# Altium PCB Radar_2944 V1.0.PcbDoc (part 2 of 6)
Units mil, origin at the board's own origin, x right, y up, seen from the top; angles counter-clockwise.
Board outline 3544.83 x 2556.65 mil, 8 copper layers (Top Layer, GND1, SIG1, PWR1, PWR2, SIG2, GND2, Bottom Layer), stack 55.2 mil thick; 301 components, 253 nets, 1055 pads, 1340 vias.
Unrouted connection lines stored in the file: 12.
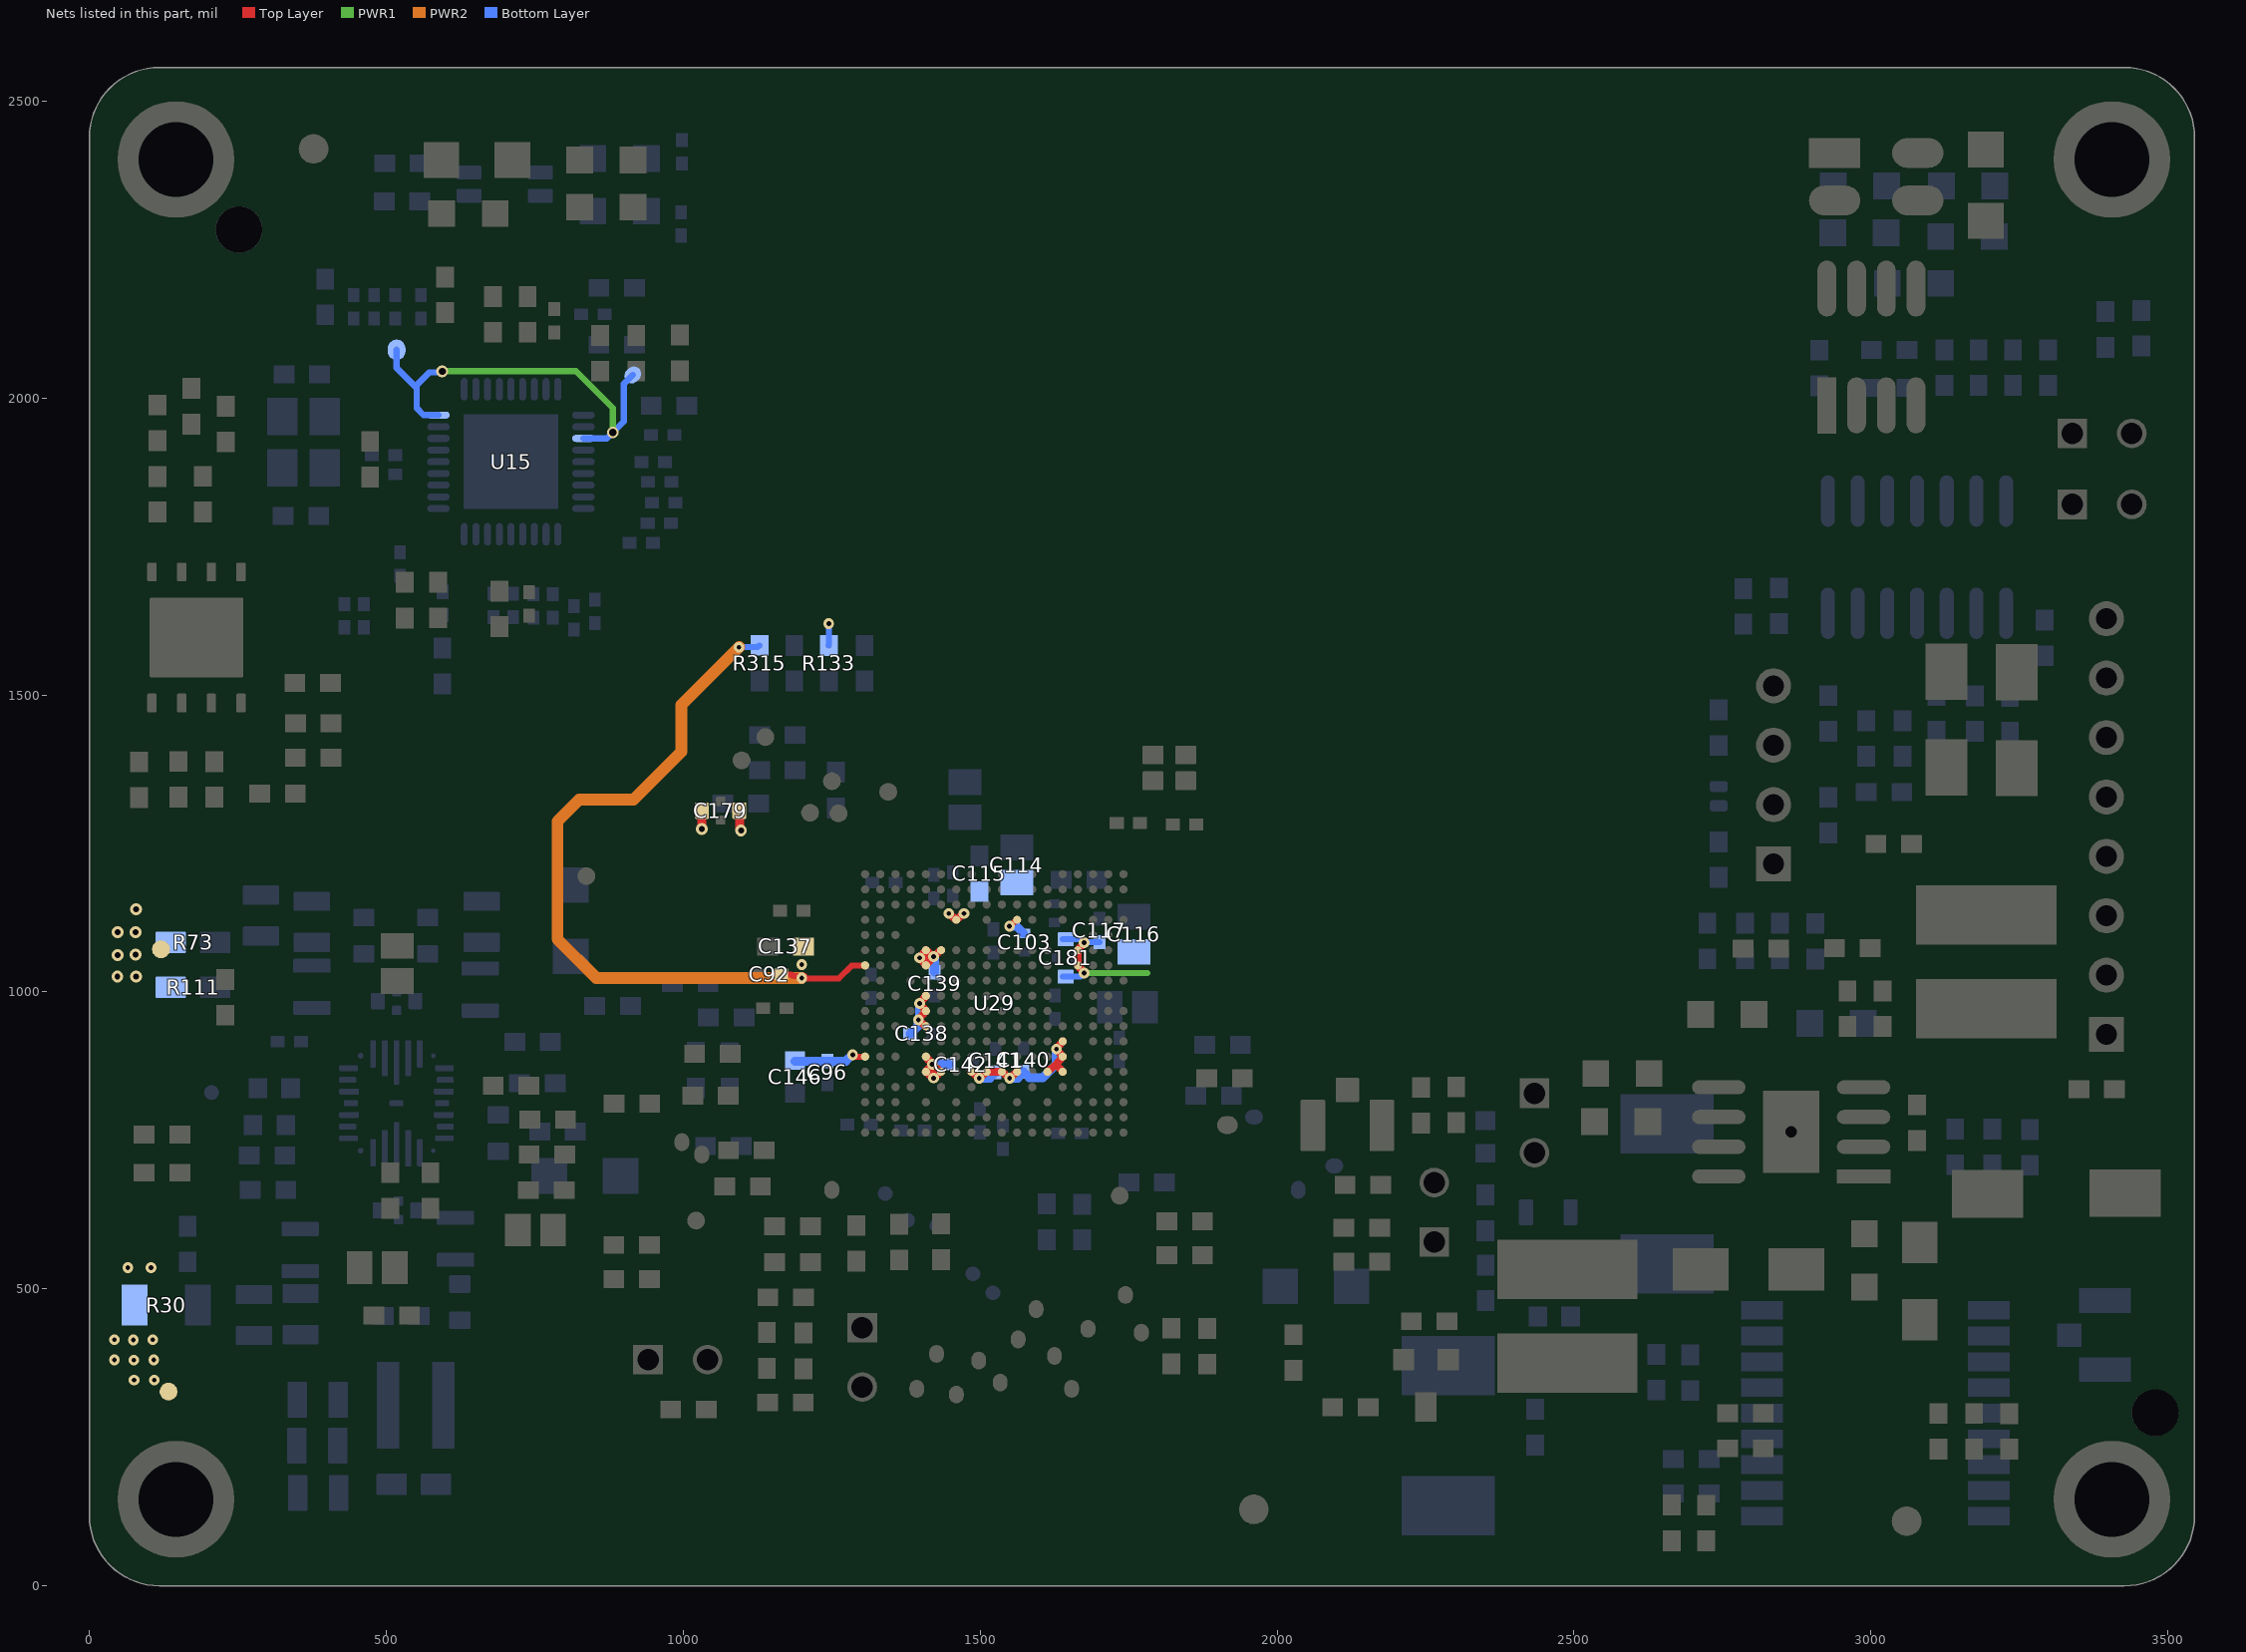
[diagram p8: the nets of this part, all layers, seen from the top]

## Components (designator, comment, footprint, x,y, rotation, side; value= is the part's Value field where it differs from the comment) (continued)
R267 "CRCW040210R0JNED" 0603 983.72,296.92 r0 top value=10
R270 "CRCW04020000Z0EDHP" 0603 502.24,2395.17 r0 bottom value=0
R271 "CRCW040210K0FKED" 0603 1883.07,910.88 r0 bottom value=10.0k
R272 "CRCW040210K0FKED" 0603 1886.6,854.78 r0 top value=10.0k
R273 "CRCW040210K0FKED" 0603 1070.9,824.97 r180 top value=10.0k
R275 "ERJ-P06F1001V" 0805 825.64,2400.56 r0 top value=1.00k
R276 "CRCW04022K94FKED" 0603 1036.73,1015.17 r180 bottom value=2.94k
R277 "CRCW04022K94FKED" 0603 1021.31,843.39 r90 bottom value=2.94k
R278 "CRCW0402100KFKED" 0603 1612.22,637.98 r270 bottom value=100k
R279 "CRCW0402100KFKED" 0603 1671.61,637.58 r270 bottom value=100k
R280 "CRCW04022K20JNED" 0603 594.45,1573.76 r270 bottom value=2.2k
R281 "ERJ-P06F1001V" 0805 825.64,2321.31 r0 top value=1.00k
R282 "CRCW0805100KJNEA" 0805 593.31,2310.39 r0 top value=100k
R291 "ERJ-2GE0R00X" 0603 165.54,600.43 r270 bottom value=0
R292 "CRCW04022K20JNED" 0603 779.35,846.19 r180 bottom value=2.2k
R309 "CRCW040210K0FKED" 0603 1819.45,556.76 r0 top value=10.0k
R312 "CRCW040210K0FKED" 0603 1869.45,613.76 r180 top value=10.0k
R315 "CRCW04021K00FKED" 0603 1128.42,1528.52 r90 bottom value=1.00k
R316 "ERJ-2GE0R00X" 0603 1133.51,1373.6 r0 bottom value=0
R326 "CRCW040210K0FKED" 0603 1074.9,672.54 r0 top value=10.0k
R331 "CRCW04021K00FKED" 0603 1882.33,378.28 r90 top value=1.00k
R332 "CRCW04021K00FKED" 0603 2943.45,1073.76 r0 top value=1.00k
R333 "ERJ-2GEJ101X" 0603 2169.45,674.76 r180 top value=100
R334 "CRCW02010000Z0ED" 0603 2167.45,602.76 r180 top value=0
R335 "CRCW040210K0FKED" 0603 2117.45,545.76 r0 top value=10.0k
R347 "ERJ-2GEJ511X" 0603 2242.09,784.19 r90 top value=510
R350 "NC.10K" 0402 516.58,2208 r0 bottom value=10.0k
R380 "CRCW040233R2FKED" 0603 1042.45,740.76 r0 bottom value=33.2
R381 "CRCW040233R2FKED" 0603 1024.22,895.77 r0 top value=33.2
R386 "CRCW040233R2FKED" 0603 1918.03,824.97 r180 bottom value=33.2
R392 "CRCW040233R2FKED" 0603 1081.13,733.32 r0 top value=33.2
R409 "CRCW040210K0FKED" 0603 2350.98,535.04 r270 bottom value=10.0k
RC31 "1K" 0603 2743.51,1469.88 r270 bottom
RC32 "1K" 0603 2928.04,1272.69 r90 bottom
RC33 "1K" 0603 2743.51,1247.68 r270 bottom
RCN1 "10K" 0805 3027.45,2192.77 r0 bottom
RCN2 "10K" 0805 3207.45,2271.76 r180 bottom
RCN3 "10K" 0805 3026.39,2356.76 r180 bottom
RCN4 "120R" 1206 3193.15,2358.02 r270 top
RCN5 "10K" 0805 3208.45,2356.76 r180 bottom
RCN11 "10K" 0603 1202.56,420.61 r270 top
RCN12 "10K" 0603 1159.01,605.45 r0 top
RCN13 "10K" 0603 2724.52,1060.75 r90 bottom
RCN14 "10K" 0603 1147.01,308.76 r0 top
RCN15 "10K" 0603 2846.47,1110.73 r270 bottom
RCN17 "100k" 0603 2788.1,1060.75 r90 bottom
RCN18 "100k" 0603 1159.01,544.86 r0 top
RCN19 "100k" 0603 1140.74,421.35 r270 top
RCN24 "NC.0" 0603 1197.56,485.87 r180 top
RCN25 "0" 0603 2906.19,1060.14 r90 bottom
RG1 "10K" 0603 2813.54,231.54 r180 top
RG2 "10" 0603 2813.54,290.49 r180 top
RG9 "10" 0603 2638.45,384.76 r270 bottom
RGP1 "100" 0603 2722.19,155.54 r180 bottom
RGP2 "100" 0603 2722.19,213.41 r180 bottom
Rs301 "CRCW040210K0FKED" 0603 2845,1625 r90 bottom value=10.0k
Rs303 "CRCW040210K0FKED" 0603 2785,1674 r270 bottom value=10.0k
TP8 "TESTPOINT" TP_25MIL-SMT 205.67,830.62 r270 bottom
TRS1 "B82793S0513N201" TRS1 3034.6,2233.79 r90 top
TVS2 "SMF30A" DIODE3715 3082,513 r90 top
U5 "TCAN1043ADYYRQ1" D014_N 3077.45,1732 r270 bottom
U6 "SCT2632QSTER" PSOP-PAD 2865.53,764.38 r180 top
U8 "LP877451A1RXVRQ1" RXV0028A 640.11,792.6 r180 bottom
U9 "GD25B64CWAG" WSON-8L 131.93,1763.86 r270 top
U15 "DP83TC812R-Q1" TJA1100 864.96,2059.6 r270 bottom
U27 "TPS78417QDBVRQ1" DBV0005A-MFG 2456.45,577.76 r90 bottom
U29 "XA2944BGALT" 0-MFG 1523.74,980.65 r270 top locked
UCAN1 "TJ1051T/3" TJ1051T/3 3139.7,2103.46 r180 top
Y3 "FW4000044Q" FP-FW4000044Q_4-SMD-2.0x1.6mm-MFG 1818.6,1377.23 r0 top
YE7 "25M" 3225 362.25,1830.6 r180 bottom

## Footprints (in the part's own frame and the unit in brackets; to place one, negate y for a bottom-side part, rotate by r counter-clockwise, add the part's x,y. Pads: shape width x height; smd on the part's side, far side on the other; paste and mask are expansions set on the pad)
0-MFG [mm]
  round 0.35 smd paste+0 mask+0.05: A1(-5.525,5.525) A2(-4.875,5.525) A4(-3.575,5.525) A6(-2.275,5.525) A8(-0.975,5.525) A10(0.325,5.525) A11(0.975,5.525) A12(1.625,5.525) A13(2.275,5.525) A14(2.925,5.525) A15(3.575,5.525) A16(4.225,5.525) A17(4.875,5.525) A18(5.525,5.525) B1(-5.525,4.875) B2(-4.875,4.875) B3(-4.225,4.875) B4(-3.575,4.875) B5(-2.925,4.875) B6(-2.275,4.875) B7(-1.625,4.875) B8(-0.975,4.875) B9(-0.325,4.875) B10(0.325,4.875) B11(0.975,4.875) B12(1.625,4.875) B13(2.275,4.875) B14(2.925,4.875) B15(3.575,4.875) B16(4.225,4.875) B17(4.875,4.875) B18(5.525,4.875) C1(-5.525,4.225) C2(-4.875,4.225) C3(-4.225,4.225) C4(-3.575,4.225) C5(-2.925,4.225) C6(-2.275,4.225) C7(-1.625,4.225) C8(-0.975,4.225) C9(-0.325,4.225) C10(0.325,4.225) C11(0.975,4.225) C12(1.625,4.225) C14(2.925,4.225) C16(4.225,4.225) C17(4.875,4.225) C18(5.525,4.225) D1(-5.525,3.575) D2(-4.875,3.575) D3(-4.225,3.575) D6(-2.275,3.575) D7(-1.625,3.575) D9(-0.325,3.575) D11(0.975,3.575) D13(2.275,3.575) D15(3.575,3.575) D16(4.225,3.575) D17(4.875,3.575) D18(5.525,3.575) E1(-5.525,2.925) E2(-4.875,2.925) E3(-4.225,2.925) E4(-3.575,2.925) E11(0.975,2.925) E12(1.625,2.925) E13(2.275,2.925) E14(2.925,2.925) E15(3.575,2.925) E17(4.875,2.925) E18(5.525,2.925) F2(-4.875,2.275) F3(-4.225,2.275) F6(-2.275,2.275) F7(-1.625,2.275) F8(-0.975,2.275) F9(-0.325,2.275) F10(0.325,2.275) F11(0.975,2.275) F12(1.625,2.275) F13(2.275,2.275) F14(2.925,2.275) F16(4.225,2.275) F17(4.875,2.275) F18(5.525,2.275) G1(-5.525,1.625) G2(-4.875,1.625) G3(-4.225,1.625) G4(-3.575,1.625) G6(-2.275,1.625) G7(-1.625,1.625) G8(-0.975,1.625) G9(-0.325,1.625) G10(0.325,1.625) G11(0.975,1.625) G12(1.625,1.625) G13(2.275,1.625) G14(2.925,1.625) G15(3.575,1.625) G17(4.875,1.625) G18(5.525,1.625) H2(-4.875,0.975) H3(-4.225,0.975) H4(-3.575,0.975) H6(-2.275,0.975) H7(-1.625,0.975) H8(-0.975,0.975) H9(-0.325,0.975) H10(0.325,0.975) H11(0.975,0.975) H12(1.625,0.975) H13(2.275,0.975) H14(2.925,0.975) H16(4.225,0.975) H17(4.875,0.975) H18(5.525,0.975) J1(-5.525,0.325) J2(-4.875,0.325) J3(-4.225,0.325) J6(-2.275,0.325) J7(-1.625,0.325) J8(-0.975,0.325) J9(-0.325,0.325) J10(0.325,0.325) J11(0.975,0.325) J12(1.625,0.325) J13(2.275,0.325) J14(2.925,0.325) J15(3.575,0.325) J17(4.875,0.325) J18(5.525,0.325) K2(-4.875,-0.325) K3(-4.225,-0.325) K4(-3.575,-0.325) K6(-2.275,-0.325) K7(-1.625,-0.325) K8(-0.975,-0.325) K9(-0.325,-0.325) K10(0.325,-0.325) K11(0.975,-0.325) K12(1.625,-0.325) K13(2.275,-0.325) K14(2.925,-0.325) K16(4.225,-0.325) K17(4.875,-0.325) K18(5.525,-0.325) L1(-5.525,-0.975) L2(-4.875,-0.975) L3(-4.225,-0.975) L6(-2.275,-0.975) L7(-1.625,-0.975) L8(-0.975,-0.975) L9(-0.325,-0.975) L10(0.325,-0.975) L11(0.975,-0.975) L12(1.625,-0.975) L13(2.275,-0.975) L14(2.925,-0.975) L15(3.575,-0.975) L17(4.875,-0.975) L18(5.525,-0.975) M2(-4.875,-1.625) M3(-4.225,-1.625) M4(-3.575,-1.625) M6(-2.275,-1.625) M7(-1.625,-1.625) M8(-0.975,-1.625) M9(-0.325,-1.625) M10(0.325,-1.625) M11(0.975,-1.625) M12(1.625,-1.625) M13(2.275,-1.625) M14(2.925,-1.625) M16(4.225,-1.625) M17(4.875,-1.625) M18(5.525,-1.625) N1(-5.525,-2.275) N2(-4.875,-2.275) N3(-4.225,-2.275) N6(-2.275,-2.275) N7(-1.625,-2.275) N8(-0.975,-2.275) N9(-0.325,-2.275) N10(0.325,-2.275) N11(0.975,-2.275) N12(1.625,-2.275) N13(2.275,-2.275) N14(2.925,-2.275) N15(3.575,-2.275) N17(4.875,-2.275) N18(5.525,-2.275) P1(-5.525,-2.925) P2(-4.875,-2.925) P3(-4.225,-2.925) P6(-2.275,-2.925) P7(-1.625,-2.925) P8(-0.975,-2.925) P9(-0.325,-2.925) P10(0.325,-2.925) P11(0.975,-2.925) P12(1.625,-2.925) P13(2.275,-2.925) P14(2.925,-2.925) P16(4.225,-2.925) P17(4.875,-2.925) P18(5.525,-2.925) R1(-5.525,-3.575) R2(-4.875,-3.575) R3(-4.225,-3.575) R4(-3.575,-3.575) R6(-2.275,-3.575) R8(-0.975,-3.575) R10(0.325,-3.575) R12(1.625,-3.575) R14(2.925,-3.575) R15(3.575,-3.575) R17(4.875,-3.575) R18(5.525,-3.575) T1(-5.525,-4.225) T2(-4.875,-4.225) T3(-4.225,-4.225) T5(-2.925,-4.225) T7(-1.625,-4.225) T9(-0.325,-4.225) T11(0.975,-4.225) T13(2.275,-4.225) T15(3.575,-4.225) T16(4.225,-4.225) T17(4.875,-4.225) T18(5.525,-4.225) U1(-5.525,-4.875) U2(-4.875,-4.875) U3(-4.225,-4.875) U4(-3.575,-4.875) U5(-2.925,-4.875) U6(-2.275,-4.875) U7(-1.625,-4.875) U8(-0.975,-4.875) U9(-0.325,-4.875) U10(0.325,-4.875) U11(0.975,-4.875) U12(1.625,-4.875) U13(2.275,-4.875) U14(2.925,-4.875) U15(3.575,-4.875) U16(4.225,-4.875) U17(4.875,-4.875) U18(5.525,-4.875) V1(-5.525,-5.525) V2(-4.875,-5.525) V3(-4.225,-5.525) V4(-3.575,-5.525) V5(-2.925,-5.525) V6(-2.275,-5.525) V7(-1.625,-5.525) V8(-0.975,-5.525) V9(-0.325,-5.525) V10(0.325,-5.525) V11(0.975,-5.525) V12(1.625,-5.525) V13(2.275,-5.525) V14(2.925,-5.525) V15(3.575,-5.525) V16(4.225,-5.525) V17(4.875,-5.525) V18(5.525,-5.525)
  silkscreen extent -6.97,-6.12 6.12,6.12, body extent -6.58,-6.58 6.58,6.58, height 0.25
100uF [mm]
  rect 2.54x4 smd: 1(-3.048,0) 2(2.952,0)
  silkscreen extent -5.84,-2.54 4.77,2.55
0402 [mm]
  rect 0.5x0.6 smd: 1(-0.038,1.888) 2(-0.038,0.888)
  silkscreen extent -0.39,0.49 0.31,2.29, body extent -0.34,0.84 0.26,1.94, height 0.6
0603 [mil]
  rect 35x30 smd: 1(-5,0) 2(55,0)
  silkscreen extent -30,-25 80,25
0603L [mm] "0603 from SM-752 data"
  rect 0.8x0.85 smd: 1(-0.7,0) 2(0.7,0)
  silkscreen extent -0.07,-0.33 0.07,0.33, body extent -0.87,-0.47 0.87,0.47, height 1
0805 [mil]
  rect 45x45 smd: 1(0,0) 2(90,0)
  silkscreen extent -35,-35 124,35
0805_155 [mm] "SMD, 2-Leads, Body 2x1.25mm"
  rrect12% 0.825x1.55 smd: 1(-0.875,0) 2(0.875,0)
  silkscreen extent -0.15,-0.77 0.15,0.77, body extent -1.15,-0.77 1.15,0.77, height 1.55
0805L [mm]
  rect 1.1x1.4 smd: 1(-0.905,1.608) 2(0.595,1.608)
  silkscreen extent -1.58,0.81 1.27,2.41, body extent -1.25,0.88 0.94,2.33, height 1.45
1206 [mil]
  rect 60x60 smd: 1(-60,0) 2(60,0)
  silkscreen extent -100,-40 100,40
1206L [mm] "1206 from SM-752 data"
  rect 1.1x1.75 smd: 1(-1.35,0) 2(1.35,0)
  silkscreen extent -0.4,-0.77 0.4,0.77, body extent -1.7,-0.9 1.7,0.9, height 1.35
2016 [mm]
  rrect17% 1.6x0.6 smd far side: 1(1.942,0.914) 2(1.942,-0.886)
  body extent 1.04,-1.09 2.84,1.11, height 1
3225 [mm]
  rect 1.3x1.6 smd: 1(-0.86,3.505) 2(0.94,1.305) 3(-0.86,1.305) 4(0.94,3.505)
  silkscreen extent -2.02,0.81 1.29,4.79
ACT1210L-201-2P-TL00 [mm]
  rrect17% 1.05x0.6 smd paste+0 mask+0: 1(-1.55,2.778) 2(-1.55,1.778) 3(1.5,1.778) 4(1.5,2.778)
  silkscreen extent -1.85,0.93 1.68,4.15, body extent -1.97,1.03 1.93,3.53, height 2.5
"CAP.2/.4 - duplicate" [mil]
  rect 80x120 smd: 1(-41,-295) 2(-42,-63)
  silkscreen extent -179,-319 97,-38
D014_N [mm] "SOIC, 14-Leads, Body 8.7x3.9mm, Pitch 1.27m"
  oval 2.2x0.6 smd: 1(-2.4,3.81) 2(-2.4,2.54) 3(-2.4,1.27) 4(-2.4,0) 5(-2.4,-1.27) 6(-2.4,-2.54) 7(-2.4,-3.81) 8(2.4,-3.81) 9(2.4,-2.54) 10(2.4,-1.27) 11(2.4,0) 12(2.4,1.27) 13(2.4,2.54) 14(2.4,3.81)
  silkscreen extent -4.31,-4.57 2.41,4.57
DBV0005A-MFG [mm]
  rrect17% 1.1x0.6 smd paste+0 mask+0: 1(-1.3,0.95) 2(-1.3,0) 3(-1.3,-0.95) 4(1.3,-0.95) 5(1.3,0.95)
  silkscreen extent -1.5,-1.53 0.87,2.01, body extent -1.4,-1.45 1.4,1.45, height 1.45
DIOD-ES1D [mm] "D?"
  rect 1.8x2.4 smd: A(0,4.1) K(0,0)
  silkscreen extent -1.3,-1.9 1.3,5.7
DIODE3715 [mil]
  rect 70x60 smd: A(-65,0) K(65,0)
  silkscreen extent -110,-40 110,40
FP-FW4000044Q_4-SMD-2.0x1.6mm-MFG [mm]
  rrect13% 0.9x0.8 smd paste+0 mask+0: 1(-0.7,-0.55) 2(0.7,-0.55) 3(0.7,0.55) 4(-0.7,0.55)
  silkscreen extent -1,-1.89 1,1.35, body extent -1.25,-1.05 1.25,1.05, height 0.25
FP-GCJ188C70J475KE02J_0603-MFG [mm]
  rrect13% 0.75x0.9 smd paste+0 mask+0: 1(-0.775,0) 2(0.775,0)
  silkscreen extent -0.9,-0.87 0.9,0.87, body extent -0.8,-0.4 0.8,0.4, height 1
FP-GRT155R70J105KE01D_0402-MFG [mm]
  rrect25% 0.4x0.5 smd paste+0 mask+0: 1(-0.4,0) 2(0.4,0)
  silkscreen extent -0.53,-0.63 0.53,0.63, body extent -0.5,-0.25 0.5,0.25, height 0.55
FP-HCJ0603ZT0R00_0603-MFG [mm]
  rrect11% 1.3x0.92 smd paste+0 mask+0: 1(-0.95,0) 2(0.95,0)
  silkscreen extent -0.9,-0.83 0.9,0.83, body extent -0.8,-0.4 0.8,0.4, height 0.7
FP-NFM18HC105C1C3D_0603-MFG [mm]
  rrect17% 0.6x0.7 smd paste+0 mask+0: 1(-0.8,0) 3(0.8,0)
  rrect25% 0.4x0.4 smd paste+0 mask+0: 2(0,-0.4) 2(0,0.4)
  silkscreen extent -1.66,-0.97 0.85,0.97, body extent -0.8,-0.4 0.8,0.4, height 0.7
"FP-TFM201610ALMAR24MTAA_0806 (2016 Metric)-MFG" [mm]
  rrect17% 0.6x1.6 smd paste+0 mask+0: 1(-0.9,0) 2(0.9,0)
  silkscreen extent -0.23,-0.9 0.23,0.9, body extent -1,-0.8 1,0.8, height 1
HDR1X4 [mm] "Connector; Header; 4 Position"
  rect 1.5x1.5 hole 0.9: 1(0,0)
  round 1.5 hole 0.9: 2(2.54,0) 3(5.08,0) 4(7.62,0)
  silkscreen extent -1.27,-1.27 8.89,1.27
HDR1X8 [mm] "Connector; Header; 8 Position"
  rect 1.5x1.5 hole 0.9: 1(0,0)
  round 1.5 hole 0.9: 2(2.54,0) 3(5.08,0) 4(7.62,0) 5(10.16,0) 6(12.7,0) 7(15.24,0) 8(17.78,0)
  silkscreen extent -1.27,-1.27 19.05,1.27
Johnson_128-0711-201 [mm] "UMC Straight Jack Receptacle, 50 Ohm, SMT"
  rrect10% 1x1.05 smd: 1(0,1.525)
  rrect10% 1.05x2.2 smd: 2(-1.475,0) 3(1.475,0)
  silkscreen extent -0.6,-1.3 0.6,-1.3, body extent -1.5,-1.55 1.5,1.55, height 1.25
"L=47UH - small" [mil]
  rect 100x236.22 smd: 1(-78,0) 2(80,0)
  silkscreen extent -138,-136 138,135
LED1 [mil]
  rect 35x30 smd: 1(-5,0) 2(55,0)
  silkscreen extent -70,-25 80,25
"MAX M8Q" [mm]
  rect 1.8x0.8 smd: 1(0,0) 2(0,1.1) 3(0,2.2) 4(0,3.3) 5(0,4.4) 6(0,5.5) 7(0,6.6) 8(0,7.7) 9(0,8.8) 10(-9.7,8.8) 11(-9.7,7.7) 12(-9.7,6.6) 13(-9.7,5.5) 14(-9.7,4.4) 15(-9.7,3.3) 16(-9.7,2.2) 17(-9.7,1.1) 18(-9.7,0)
  silkscreen extent -9.74,-1 0.01,9.8
Net-Tie_50milWide_30milLong [mil] "50mil net tie, no solder mask opening, no solder paste"
  rect 30x50 on Mid5 paste-20 mask-20: 1(-15,0) 2(15,0)
PSOP-PAD [mil]
  rect 94.49x137.8 hole 20: 0(0,0)
  rect 90x24 smd: 1(-122.05,75)
  oval 90x24 smd: 2(-122.05,25) 3(-122.05,-25) 4(-122.05,-75) 5(122.05,-75) 6(122.05,-25) 7(122.05,25) 8(122.05,75)
  silkscreen extent -120,-110 125,110
RXV0028A [mm]
  round 0.195 smd paste+0 mask+0: 1(1.55,2.536) 9(1.55,-1.524)
  rrect40% 0.8x0.25 smd paste+0 mask+0: 2(1.073,2.006) 8(1.073,-0.994) 16(5.173,-0.994) 22(5.173,2.006)
  rrect40% 0.725x0.25 smd paste+0 mask+0: 3(1.036,1.506) 7(1.036,-0.494) 17(5.211,-0.494) 21(5.211,1.506)
  rrect40% 0.85x0.25 smd paste+0 mask+0: 4(1.098,1.006) 6(1.098,0.006) 18(5.148,0.006) 20(5.148,1.006)
  rrect40% 0.6x0.25 smd paste+0 mask+0: 5(1.173,0.506) 19(3.123,0.506) 19(5.073,0.506)
  rrect40% 0.25x1.175 smd paste+0 mask+0: 10(2.123,-1.607) 14(4.123,-1.607) 24(4.123,2.618) 28(2.123,2.618)
  rrect40% 0.25x1.55 smd paste-1000 mask+0: 11(2.623,-1.419) 13(3.623,-1.419) 25(3.623,2.431) 27(2.623,2.431)
  rrect40% 0.25x1.9 smd paste-1000 mask+0: 12(3.123,-1.244) 26(3.123,2.256)
  round 0.243 smd paste+0 mask+0: 15(4.653,-1.524) 23(4.653,2.536)
  Top Layer region: 0.673,0.581 0.68,0.606 0.698,0.624 0.723,0.631 0.723,0.631 2.498,0.631 2.498,0.906 3.748,0.906 3.748,0.631 5.523,0.631 5.548,0.624 5.566,0.606 5.573,0.581 5.573,0.581 5.573,0.431 5.566,0.406 5.548,0.388 5.523,0.381 5.523,0.381 3.748,0.381 3.748,0.106 2.498,0.106 2.498,0.381 0.723,0.381 0.698,0.388 0.68,0.406 0.673,0.431 0.673,0.431
  Top Layer region: 5.573,2.581 5.566,2.606 5.548,2.624 5.523,2.631 5.523,2.631 4.748,2.631 4.748,3.156 4.741,3.181 4.723,3.199 4.698,3.206 4.698,3.206 4.548,3.206 4.523,3.199 4.505,3.181 4.498,3.156 4.498,3.156 4.498,2.431 4.502,2.412 4.513,2.396 4.529,2.385 4.548,2.381 4.548,2.381 5.523,2.381 5.542,2.385 5.558,2.396 5.569,2.412 5.573,2.431 5.573,2.431
  Top Layer region: 5.573,-1.569 5.566,-1.594 5.548,-1.612 5.523,-1.619 5.523,-1.619 4.748,-1.619 4.748,-2.144 4.741,-2.169 4.723,-2.187 4.698,-2.194 4.698,-2.194 4.548,-2.194 4.523,-2.187 4.505,-2.169 4.498,-2.144 4.498,-2.144 4.498,-1.419 4.502,-1.4 4.513,-1.384 4.529,-1.373 4.548,-1.369 4.548,-1.369 5.523,-1.369 5.542,-1.373 5.558,-1.384 5.569,-1.4 5.573,-1.419 5.573,-1.419
  Top Layer region: 0.673,-1.569 0.68,-1.594 0.698,-1.612 0.723,-1.619 0.723,-1.619 1.498,-1.619 1.498,-2.144 1.505,-2.169 1.523,-2.187 1.548,-2.194 1.548,-2.194 1.698,-2.194 1.717,-2.19 1.733,-2.179 1.744,-2.163 1.748,-2.144 1.748,-2.144 1.748,-1.419 1.744,-1.4 1.733,-1.384 1.717,-1.373 1.698,-1.369 1.698,-1.369 0.723,-1.369 0.704,-1.373 0.688,-1.384 0.677,-1.4 0.673,-1.419 0.673,-1.419
  Top Layer region: 0.673,2.581 0.68,2.606 0.698,2.624 0.723,2.631 0.723,2.631 1.498,2.631 1.498,3.156 1.505,3.181 1.523,3.199 1.548,3.206 1.548,3.206 1.698,3.206 1.717,3.202 1.733,3.191 1.744,3.175 1.748,3.156 1.748,3.156 1.748,2.431 1.744,2.412 1.733,2.396 1.717,2.385 1.698,2.381 1.698,2.381 0.723,2.381 0.704,2.385 0.688,2.396 0.677,2.412 0.673,2.431 0.673,2.431
  silkscreen extent 0,-2.59 5.42,3.61, body extent 0.87,-1.99 5.37,3.01, height 1
SIP2 [mil]
  rect 50x50 hole 36: 1(0,0)
  round 50 hole 36: 2(100,0)
  silkscreen extent -50,-50 150,50
SMB-ATA3 [mm] "CONN_UFL-R-SMT-1"
  rect 1.05x1 smd: 1(4.675,0.61)
  rect 2.2x1.05 smd: 2(3.15,-0.865) 2(3.15,2.085)
  Top Layer keep-out region: 3.95,-0.091 2.05,-0.091 2.05,1.309 3.95,1.309
  silkscreen extent 1.45,-1.09 4.85,2.31, body extent 1.6,-0.89 4.7,2.11, height 1.27
SOD-882 [mm] "Skyworks"
  rrect42% 0.475x0.75 smd mask+0.05: 1(-0.412,0) 2(0.412,0)
  silkscreen extent -1.1,-0.35 -0.87,0.35, body extent -0.5,-0.3 0.5,0.3, height 0.5
SOT-23 [mil]
  rect 36x36 smd: 1(0,0) 2(75,0)
  rect 36x50 smd: 3(38,80)
  silkscreen extent -20,-5 95,85
TJ1051T/3 [mm]
  rect 0.8x2.4 smd: 1(5.436,2.946)
  oval 0.8x2.4 smd: 2(4.166,2.946) 3(2.896,2.946) 4(1.626,2.946) 5(1.626,-2.054) 6(2.896,-2.054) 7(4.166,-2.054) 8(5.436,-2.054)
  silkscreen extent 0.73,-1.55 6.33,2.45
TJA1100 [mil] "QFN50P600X600-36V4N"
  oval 11.81x38 smd: 1(245.83,277.09) 2(226.15,277.09) 3(206.46,277.09) 4(186.78,277.09) 5(167.09,277.09) 6(147.41,277.09) 7(127.72,277.09) 8(108.04,277.09) 9(88.35,277.09) 19(88.35,32.91) 20(108.04,32.91) 21(127.72,32.91) 22(147.41,32.91) 23(167.09,32.91) 24(186.78,32.91) 25(206.46,32.91) 26(226.15,32.91) 27(245.83,32.91)
  oval 38x11.81 smd: 10(45,233.74) 11(45,214.06) 12(45,194.37) 13(45,174.69) 14(45,155) 15(45,135.32) 16(45,115.63) 17(45,95.94) 18(45,76.26) 28(289.19,76.26) 29(289.19,95.94) 30(289.19,115.63) 31(289.19,135.32) 32(289.19,155) 33(289.19,174.69) 34(289.19,194.37) 35(289.19,214.06) 36(289.19,233.74)
  rect 159.45x159.45 smd: 37(167.09,155)
  silkscreen extent 45,33 289,315, body extent 46,34 288,276, height 39
TP_25MIL-SMT [mil]
  round 25 smd paste-25 mask-2.5: 1(0,0)
TRS1 [mm] "B82793S0513N201"
  rect 1.27x2.2 smd: 1(4.541,2.432)
  oval 1.27x2.2 smd: 2(2.509,2.432) 3(2.509,-1.124) 4(4.541,-1.124)
  silkscreen extent 1.49,-2.65 5.56,3.96
WSON-8L [mm]
  rrect25% 0.8x0.4 smd: 1(1.447,3.137) 2(1.447,1.867) 3(1.447,0.597) 4(1.447,-0.673) 5(7.047,-0.673) 6(7.047,0.597) 7(7.047,1.867) 8(7.047,3.137)
  rrect3% 3.4x4 smd paste-3: 9(4.247,1.232)
  rrect7% 1.468x1.698 on Top Paste: ""(3.413,2.181) ""(3.413,0.283) ""(5.081,2.181) ""(5.081,0.283)
  silkscreen extent 1.05,-1.47 7.45,3.93, body extent 1.2,-1.32 7.3,3.78, height 0.8
XAL4030 [mil] "Coilcraft XAL4030 7/18/12"
  rect 38x146 smd: 1(-46.5,0) 2(46.5,0)
  silkscreen extent -85,-85 85,85, body extent -84,-84 84,84, height 122

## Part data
ATA3: library part SMB, "SMB Straight Connector"
C1 C41 Cu1 Cu2 Cu4 Cu6 Cu7: library part CAP, "Capacitor"
C3 C123 C146 C149: library part CMP-0007134-5, "CAP, CERM, 2.2 uF, 6.3 V, +/- 10%, X7R, AEC-Q200 Grade 1, 0603", Cap_Case=0603, Manufacturer=MuRata, Supplier Part Number 1=490-5316-1-ND, TempCo=X7R, Tolerance_%=10%, Value1=Unknown, Value2=6.3V, ValueDisplayed=2.2uF
C5 C92 C96 C107 C111 C113 C115 C117 C138 C139 C140 C141 C142 C163 C164 C165 C168 C170 C172 C174 C175 C176 C177: library part CMP-0078265-1, "CAP, CERM, 0.22 µF, 16 V,+/- 10%, X7R, AEC-Q200 Grade 1, 0402", Cap_Case=0402, Manufacturer=MuRata, Supplier Part Number 1=490-10671-1-ND, TempCo=X7R, Tolerance_%=10%, Value2=16V, ValueDisplayed=0.22µF
C6 C8 C124 C144 C153: library part CMP-0091520-1, "Cap Ceramic Multilayer 4.7uF 6.3V DC 10% SMD Paper T/R", Manufacturer=Murata, Operating Temperature Range="-55°C to +125°C", TempCo=22%, Temperature Characteristic=X7S, Tolerance_%=10%, ValueDisplayed=4.7uF
C7 C31 C110 C112 C114 C116 C120: library part Capacitor, "CAP, CERM, 10 uF, 10 V, +/- 10%, X7R, 0805", Cap_Case=0805, Manufacturer=MuRata, Supplier Part Number 1=490-10674-1-ND, TempCo=X7R, Tolerance_%=10%, Value1=Unknown, Value2=10V, ValueDisplayed=10uF
C8G CGP2 CN1 Cu3: library part CAP
C9 C58 C179 C181: library part CMP-0088247-2, "3 Terminals Low ESL Chip Multilayer Ceramic Capacitors for Automotive", Manufacturer=Murata, Tolerance_%=20%, ValueDisplayed=1uF
C11 C12 C105 C150 C200: library part Capacitor, "CAP, CERM, 0.1 uF, 16 V, +/- 10%, X7R, 0402", Cap_Case=0402, Manufacturer=MuRata, Supplier Part Number 1=490-4759-2-ND, TempCo=X7R, Tolerance_%=10%, Value1=Unknown, Value2=16V, ValueDisplayed=0.1uF
C13: library part Capacitor, "CAP, CERM, 4700 pF, 50 V, +/- 10%, X7R, AEC-Q200 Grade 1, 0402", Cap_Case=0402, Manufacturer=MuRata, Supplier Part Number 1=490-4915-1-ND, TempCo=X7R, Tolerance_%=10%, Value1=Unknown, Value2=50V, ValueDisplayed=4700pF
C32 C40 C51: library part Capacitor, "CAP, CERM, 0.47 uF, 50 V, +/- 10%, X7R, AEC-Q200 Grade 1, 0603", Cap_Case=0603, Manufacturer=TDK, Supplier Part Number 1=445-172475-1-ND, TempCo=X7R, Tolerance_%=10%, Value1=Unknown, Value2=50V, ValueDisplayed=0.47uF
C35 C44 C52: library part CMP-0006324-2, "CAP, CERM, 0.01 uF, 50 V, +/- 10%, X7R, AEC-Q200 Grade 1, 0402", Cap_Case=0402, Manufacturer=TDK, Supplier Part Number 1=445-6893-1-ND, TempCo=X7R, Tolerance_%=10%, Value1="0.333065 ohm", Value2=50V, ValueDisplayed=0.01uF
C80 C128: library part Capacitor, "CAP, CERM, 0.1 uF, 50 V, +/- 10%, X7R, AEC-Q200 Grade 1, 0402", Cap_Case=0402, Manufacturer=TDK, Supplier Part Number 1=445-6899-1-ND, TempCo=X7R, Tolerance_%=10%, Value1="0.039064 ohm", Value2=50V, ValueDisplayed=0.1uF
C90: library part Capacitor, "CAP, CERM, 1 uF, 16 V, +/- 10%, X7R, AEC-Q200 Grade 1, 0603", Cap_Case=0603, Manufacturer=MuRata, Supplier Part Number 1=490-5241-6-ND, TempCo=X7R, Tolerance_%=10%, Value1=Unknown, Value2=16V, ValueDisplayed=1uF
C91: library part Capacitor, "CAP, CERM, 0.1 uF, 50 V, +/- 10%, X7R, AEC-Q200 Grade 1, 0603", Cap_Case=0402, Manufacturer=TDK, Supplier Part Number 1=445-6899-1-ND, TempCo=X7R, Tolerance_%=10%, Value1="0.039064 ohm", Value2=50V, ValueDisplayed=0.1uF
C95 C121: library part Cap, "Capacitor"
C102 C103: library part CMP-0088425-1, "1µF ±10% 6.3V Ceramic Capacitor X7R 0402 (1005 Metric)", Digikey Part Number=490-18216-1-ND, Manufacturer=Murata, Mouser Part Number=81-GRT155R70J105KE1D, Operating Temperature Range="-55°C to +125°C", TempCo=15%, Temperature Characteristic=X7R, Tolerance_%=10%, ValueDisplayed=1uF
C106 C108: library part Capacitor, "CAP, CERM, 3.9 pF, 50 V, +/- 5%, C0G/NP0, 0402", Cap_Case=0402, Manufacturer=MuRata, Supplier Part Number 1=14T3295, TempCo=C0G/NP0, Tolerance_%=5%, Value1=Unknown, Value2=50V, ValueDisplayed=3.9pF
C125 C129 C130 C132 C134: library part CMP-0860846-1, "CAP, CERM, 22 µF, 6.3 V,+/- 20%, X7T, AEC-Q200 Grade 1, 0805", Alternate PartNumber=CGA4J1X7T0J226M125AC, Cap_Case=0805, Manufacturer=TDK, TempCo=X7T, Tolerance_%=20%, Value2=6.3V, ValueDisplayed=22µF
C131 C135 C136: library part CMP-0006351-2, "CAP, CERM, 0.1 uF, 16 V, +/- 10%, X7R, 0402", Cap_Case=0402, Manufacturer=MuRata, Supplier Part Number 1=490-4759-2-ND, TempCo=X7R, Tolerance_%=10%, Value1=Unknown, Value2=16V, ValueDisplayed=0.1uF
C137: library part Capacitor, "CAP, CERM, 2.2 uF, 6.3 V, +/- 10%, X7R, AEC-Q200 Grade 1, 0603", Cap_Case=0603, Manufacturer=MuRata, Supplier Part Number 1=490-5316-1-ND, TempCo=X7R, Tolerance_%=10%, Value1=Unknown, Value2=6.3V, ValueDisplayed=2.2uF
C143 C201 C202: library part CMP-0860846-1, "CAP, CERM, 22 µF, 6.3 V,+/- 20%, X7T, AEC-Q200 Grade 1, 0805", Cap_Case=0805, Manufacturer=TDK, TempCo=X7T, Tolerance_%=20%, Value2=6.3V, ValueDisplayed=22µF
C145: library part CMP-0007136-5, "CAP, CERM, 1 uF, 16 V, +/- 10%, X7R, AEC-Q200 Grade 1, 0603", Cap_Case=0603, Manufacturer=MuRata, Supplier Part Number 1=490-5241-6-ND, TempCo=X7R, Tolerance_%=10%, Value1=Unknown, Value2=16V, ValueDisplayed=1uF
C157 C161: library part Capacitor, "CAP, CERM, 0.1 uF, 100 V, +/- 10%, X7R, AEC-Q200 Grade 1, 0805", Cap_Case=0805, Manufacturer=TDK, Supplier Part Number 1=445-5827-1-ND, TempCo=X7R, Tolerance_%=10%, Value1="0.020726 ohm", Value2=100V, ValueDisplayed=0.1uF
C167: library part Capacitor, "CAP, CERM, 4700 pF, 1000 V, +/- 10%, X7R, 1206", Cap_Case=1206, Manufacturer=MuRata, Supplier Part Number 1=490-3498-1-ND, TempCo=X7R, Tolerance_%=10%, Value1=Unknown, Value2=1000V, ValueDisplayed=4700pF
C180: library part Capacitor, "CAP, CERM, 0.047 uF, 50 V, +/- 10%, X7R, AEC-Q200 Grade 1, 0402", Cap_Case=0402, Manufacturer=TDK, Supplier Part Number 1=445-6897-1-ND, TempCo=X7R, Tolerance_%=10%, Value1="0.06407 ohm", Value2=50V, ValueDisplayed=0.047uF
C199: library part Capacitor, "CAP, CERM, 0.22 µF, 16 V,+/- 10%, X7R, AEC-Q200 Grade 1, 0402", Cap_Case=0402, Manufacturer=MuRata, Supplier Part Number 1=490-10671-1-ND, TempCo=X7R, Tolerance_%=10%, Value2=16V, ValueDisplayed=0.22µF
CBG1: library part ELECTRO2
CP8 Cu5: library part CAPACITOR
D4: library part DIODE_SCHOTTKY, "Diode, Schottky,  V, 0.01 A, SOD-882", Manufacturer="Skyworks Solutions", Value1=0.01A, Value2=0.34V
D6 D12 D14 D16: library part LED, "LED, Green, SMD", Color=Green, Manufacturer=Lumex, Power_TotalModule=50mW, Value1=0.05W, Value2=2V
D8 Dr8 Dr9 TVS2: library part DIODE
D13: library part LED, "LED, Yellow, SMD", Color=yellow, Manufacturer=Rohm, Power_TotalModule=54mW, Value1=0.054W, Value2=2.2V
D15 D17: library part TPD1E0xU0x, "Automotive 1-Channel Ultra-Low-Capacitance IEC ESD Protection Diode, DPY0002A (X1SON-2)", Alternate Manufacturer="Texas Instruments", Alternate PartNumber=TPD1E05U06QDPYTQ1, Operating Temperature Range="-40 to 125 C", Rating=Automotive
DS2: library part LED, "LED, Red, SMD", Color=Red, Manufacturer=OSRAM, Value1=W, Value2=1.8V
FB1: library part SYM-BLM18AG102SH1D, "Chip Ferrite Bead, 0603, 1000Ω @ 100MHz, 0.5Ω, 25%, 450mA", Impedance At Frequency="1000Ω @ 100MHz", Manufacturer=Murata, Operating Temperature Range="-55°C to +125℃", Test Frequency=100MHz, Tolerance_%=25%
J1 PL1: library part CON2_1, "Connector"
J10 J11: library part CON2
J14: library part CMP-0055788-1, "UMC Straight Jack Receptacle, 50 Ohm, Gold, SMT", Manufacturer="Cinch Connectivity", Supplier Part Number 1=J983CT-ND
L1: library part Inductor_Iron, "Inductor, Shielded, Metal Composite, 1.5 µH, 2.3 A, 0.11 ohm, AEC-Q200 Grade 0, SMD", Manufacturer=TDK, Supplier Part Number 1=445-174575-1-ND, Value1="0.11 ohm", Value2=2.3A, ValueDisplayed=1.5µH
L2 L8 L9: library part CMP-0091696-1, "240nH Shielded Thin Film Inductor 5A 23mOhm Max 0806 (2016 Metric)", Digikey Part Number=445-181484-1-ND, Manufacturer=TDK, Mouser Part Number=810-TFM201610ALMAR24, Operating Temperature Range="-55°C to +150°C", Test Frequency=1MHz, Tolerance_%=20%
L3 L4: library part INDUCTOR1
L7: library part SYM-ACT1210L-201-2P-TL00, "200µH @ 100kHz 2 Line Common Mode Choke Surface Mount 70mA DCR 5.5Ohm", Digikey Part Number=445-174934-1-ND, Impedance At Frequency="9.5kΩ @ 10MHz", Manufacturer=TDK, Mouser Part Number=810-ACT1210L-2012P00, Operating Temperature Range="-40°C to +125°C", Test Frequency=100kHz, Tolerance_%=-10/30%
L10: library part CMP-0060990-1, "Inductor, Shielded, Composite, 4.7 uH, 4.5 A, 0.0401 ohm, SMD", Manufacturer=Coilcraft, Supplier Part Number 1=994-XAL4030-472MEB, Value1="0.0401 ohm", Value2=4.5A, ValueDisplayed=4.7uH
L11: library part Inductor, "Inductor"
NT1: library part CMP-0078142-4, "Single point connection between nets.", Manufacturer=N/A
NT2 NT3 NT4: library part CMP-0078142-3, "Single point connection between nets.", Manufacturer=N/A
P1 PSO1: library part Header_2x1, "Header, 100mil, 2x1, Gold, TH", Color=Black, Current_A=6.3A, Manufacturer=Samtec, Supplier Part Number 1=SAM1029-02-ND, Voltage_V=550V
P11: "Header, 4-Pin"
PDB1: "Header, 8-Pin"
Q1: library part MOSFET_N_D3G1S2, "MOSFET, N-CH, 100 V, 0.17 A, SOT-23", Alternate Manufacturer=None, Manufacturer="Fairchild Semiconductor", Supplier Part Number 1=BSS123NCT-ND, Value1=1, Value2="1.8 nC"
R1 R7 R8 R8G R12 R56 R57 R58 RC31 RC32 RC33 RCN1 RCN2 RCN3 RCN4 RCN5 RCN11 RCN12 RCN13 RCN14 RCN15 RCN17 RCN18 RCN19 RCN24 RCN25 RG1 RG2 RG9 RGP1 RGP2: library part RES1
R3 R16 R17 R21 R22 R23 R25 R31 R37 R50 R51 R54 R63 R186 R190 R233 R246 R316: library part Resistor, "RES, 0, 5%, 0.1 W, AEC-Q200 Grade 0, 0402", Manufacturer=Panasonic, Power_W=100mW, Supplier Part Number 1=P0.0JCT-ND, TempCo="600 ppm/C", Tolerance_%=5%, Value2=0.1W, Value_Code=0000, ValueDisplayed=0
R4 R271 R272 R273 R309 R312 R326: library part CMP-0025958-3, "RES, 10.0 k, 1%, 0.063 W, AEC-Q200 Grade 0, 0402", Manufacturer=Vishay-Dale, Power_W=63mW, Supplier Part Number 1=541-10.0KLCT-ND, TempCo="100 ppm/C", Tolerance_%=1%, Value2=0.063W, Value_Code=10k0, ValueDisplayed=10.0k
R5: library part Resistor, "RES, 0, 1%, 0.1 W, AEC-Q200 Grade 0, 0603", Manufacturer="Stackpole Electronics Inc", Power_W=100mW, Supplier Part Number 1=RMCF0603ZT0R00CT-ND, TempCo=ppm/C, Tolerance_%=1%, Value2=0.1W, Value_Code=0
R11 R116 R265 R270: library part Resistor, "RES, 0, 0%, 0.2 W, AEC-Q200 Grade 0, 0402", Manufacturer=Vishay-Dale, Power_W=200mW, Supplier Part Number 1=541-0.0YBTR-ND, Tolerance_%=0%, Value2=0.2W, Value_Code=0
R14 R71 R75 R76 R291: library part CMP-0026992-3, "RES, 0, 5%, 0.1 W, AEC-Q200 Grade 0, 0402", Manufacturer=Panasonic, Power_W=100mW, Supplier Part Number 1=P0.0JCT-ND, TempCo="600 ppm/C", Tolerance_%=5%, Value2=0.1W, Value_Code=0000, ValueDisplayed=0
R15 R24: library part Resistor, "RES, 60, 1%, 0.063 W, AEC-Q200 Grade 0, 0402", Manufacturer=Vishay-Dale, Power_W=63mW, Supplier Part Number 1=541-61.9LCT-ND, TempCo="100 ppm/C", Tolerance_%=1%, Value2=0.063W, Value_Code=61R9, ValueDisplayed=60
R18 R106 R125 R264 R335 R409: library part Resistor, "RES, 10.0 k, 1%, 0.063 W, AEC-Q200 Grade 0, 0402", Manufacturer=Vishay-Dale, Power_W=63mW, Supplier Part Number 1=541-10.0KLCT-ND, TempCo="100 ppm/C", Tolerance_%=1%, Value2=0.063W, Value_Code=10k0, ValueDisplayed=10.0k
R30: library part CMP-0017253-2, "RES, 0.001, 1%, 1 W, AEC-Q200 Grade 0, 1206", Manufacturer="Stackpole Electronics Inc", Power_W=1W, Supplier Part Number 1=CSNL1206FT1L00CT-ND, TempCo="50 ppm/C", Tolerance_%=1%, Value_Code=1L000, ValueDisplayed=0.001
R34 R292: library part Resistor, "RES, 2.2 k, 5%, 0.063 W, AEC-Q200 Grade 0, 0402", Manufacturer=Vishay-Dale, Power_W=63mW, Supplier Part Number 1=541-2.2KJCT-ND, TempCo="200 ppm/C", Tolerance_%=5%, Value2=0.063W, Value_Code=2k20, ValueDisplayed=2.2k
R40 R44 R45: library part Resistor, "RES, 10.0 k, 1%, 0.063 W, AEC-Q200 Grade 0, 0603", Manufacturer=Vishay-Dale, Power_W=63mW, Supplier Part Number 1=541-10.0KLCT-ND, TempCo="100 ppm/C", Tolerance_%=1%, Value2=0.063W, Value_Code=10k0, ValueDisplayed=10.0k
R43: library part Resistor, "RES, 47k, 1%, 0.063 W, AEC-Q200 Grade 0, 0603", Manufacturer=Vishay-Dale, Power_W=63mW, Supplier Part Number 1=541-47.5KLCT-ND, TempCo="100 ppm/C", Tolerance_%=1%, Value2=0.063W, Value_Code=47k5, ValueDisplayed=47k
R46 R47 R48 R49 R61: library part SYM-ERJ-1GNF33R2C, "Res Thick Film 0603 47 Ohm 1%", Digikey Part Number=P122945CT-ND, Manufacturer=Panasonic, Mouser Part Number=667-ERJ-1GNF33R2C, Operating Temperature Range="-55°C to +125°C", Power_W=50mW, TempCo=200ppm/°C, Tolerance_%=1%
R52: library part Resistor, "RES, 3.3 k, 5%, 0.063 W, AEC-Q200 Grade 0, 0402", Manufacturer=Vishay-Dale, Power_W=63mW, Supplier Part Number 1=541-3.3KJCT-ND, TempCo="200 ppm/C", Tolerance_%=5%, Value2=0.063W, Value_Code=3k30, ValueDisplayed=3.3k
R53: library part Resistor, "RES, 4.7 k, 5%, 0.063 W, AEC-Q200 Grade 0, 0402", Manufacturer=Vishay-Dale, Power_W=63mW, Supplier Part Number 1=541-4.7KJCT-ND, TempCo="200 ppm/C", Tolerance_%=5%, Value2=0.063W, Value_Code=4k70, ValueDisplayed=4.7k
R55: library part Resistor, "RES, 33 k, 5%, 0.063 W, AEC-Q200 Grade 0, 0402", Manufacturer=Vishay-Dale, Power_W=63mW, Supplier Part Number 1=541-33KJCT-ND, TempCo="200 ppm/C", Tolerance_%=5%, Value2=0.063W, Value_Code=33k0, ValueDisplayed=33k
R73 R111 R200: library part CMP-0091690-1, "RES 0 OHM JUMPER 1/4W 0603", Digikey Part Number=HCJ0603ZT0R00CT-ND, Manufacturer="Stackpole Electronics", Operating Temperature Range="-55°C to +155°C", Power_W=250mW
R74 R96 R100 R178 R225 R230 R234 R237 R238 R239 R240 R245 R247 R249: library part SYM-ERJ-1GNF33R2C, "Res Thick Film 0201 33.2 Ohm 1% 0.05W(1/20W) ±200ppm/C Pad SMD Automotive T/R", Digikey Part Number=P122945CT-ND, Manufacturer=Panasonic, Mouser Part Number=667-ERJ-1GNF33R2C, Operating Temperature Range="-55°C to +125°C", Power_W=50mW, TempCo=200ppm/°C, Tolerance_%=1%
R79 R89: library part Resistor, "RES, 2.49 k, 1%, 0.063 W, AEC-Q200 Grade 0, 0402", Manufacturer=Vishay-Dale, PartNumber=CRCW04022K49FKED, Power_W=63mW, Supplier Part Number 1=541-2.49KLCT-ND, TempCo="100 ppm/C", Tolerance_%=1%, Value2=0.063W, Value_Code=2k49, ValueDisplayed="NC 2.49k"
R99 R103 R133 R159 R315 R331 R332: library part Resistor, "RES, 1.00 k, 1%, 0.063 W, AEC-Q200 Grade 0, 0402", Manufacturer=Vishay-Dale, Power_W=63mW, Supplier Part Number 1=541-1.00KLCT-ND, TempCo="100 ppm/C", Tolerance_%=1%, Value2=0.063W, Value_Code=1k00, ValueDisplayed=1.00k
R102 R210: library part Resistor, "RES, 10.0 k, 1%, 0.063 W, AEC-Q200 Grade 0, 0402", Manufacturer=Vishay-Dale, PartNumber=CRCW040210K0FKED, Power_W=63mW, Supplier Part Number 1=541-10.0KLCT-ND, TempCo="100 ppm/C", Tolerance_%=1%, Value2=0.063W, Value_Code=10k0, ValueDisplayed="NC 10.0k"
R104: library part SYM-HCJ0603ZT0R00, "RES 0 OHM JUMPER 1/4W 0603", Digikey Part Number=HCJ0603ZT0R00CT-ND, Manufacturer="Stackpole Electronics", Operating Temperature Range="-55°C to +155°C", Power_W=250mW
R110 R267: library part Resistor, "RES, 10, 5%, 0.063 W, AEC-Q200 Grade 0, 0402", Manufacturer=Vishay-Dale, Power_W=63mW, Supplier Part Number 1=541-10JCT-ND, TempCo="200 ppm/C", Tolerance_%=5%, Value2=0.063W, Value_Code=10R0, ValueDisplayed=10
R156: library part Resistor, "RES, 11.5 k, 1%, 0.063 W, AEC-Q200 Grade 0, 0402", Manufacturer=Vishay-Dale, Power_W=63mW, Supplier Part Number 1=541-6.04KLCT-ND, TempCo="100 ppm/C", Tolerance_%=1%, Value2=0.063W, Value_Code=6k04, ValueDisplayed=11.5k
R172: library part Resistor, "RES, 20 k, 1%, 0.063 W, AEC-Q200 Grade 0, 0402", Manufacturer=Vishay-Dale, Power_W=63mW, Supplier Part Number 1=541-10.5KLCT-ND, TempCo="100 ppm/C", Tolerance_%=1%, Value2=0.063W, Value_Code=10k5, ValueDisplayed=20k
R193 R380 R381 R392: library part Resistor, "RES, 47, 1%, 0.063 W, AEC-Q200 Grade 0, 0402", Manufacturer=Vishay-Dale, Power_W=63mW, Supplier Part Number 1=541-33.2LCT-ND, TempCo="100 ppm/C", Tolerance_%=1%, Value2=0.063W, Value_Code=33R2, ValueDisplayed=47
R218 R334: library part Resistor, "RES, 0, 5%, 0.05 W, 0201", Manufacturer=Vishay-Dale, Power_W=50mW, Supplier Part Number 1=72M6743, TempCo=ppm/C, Tolerance_%=5%, Value2=0.05W, Value_Code=0000, ValueDisplayed=0
R242 R333: library part Resistor, "RES, 100, 5%, 0.1 W, AEC-Q200 Grade 0, 0402", Manufacturer=Panasonic, Power_W=100mW, Supplier Part Number 1=P100JCT-ND, TempCo="200 ppm/C", Tolerance_%=5%, Value2=0.1W, Value_Code=100R, ValueDisplayed=100
R248: library part Resistor, "NC RES, 1.00 M, 1%", Manufacturer=Vishay-Dale, Power_W=100mW, Supplier Part Number 1=541-1.00MHCT-ND, TempCo="100 ppm/C", Tolerance_%=1%, Value2=0.1W, Value_Code=1M00, ValueDisplayed="NC 1.00M"
R251 R255: library part Resistor, "RES, 2.49 k, 1%, 0.063 W, AEC-Q200 Grade 0, 0402", Manufacturer=Vishay-Dale, PartNumber=CRCW04022K49FKED, Power_W=63mW, Supplier Part Number 1=541-2.49KLCT-ND, TempCo="100 ppm/C", Tolerance_%=1%, Value2=0.063W, Value_Code=2k49, ValueDisplayed=NC.2.49k
R253 R254 R256 R257: library part Resistor, "RES, 2.49 k, 1%, 0.063 W, AEC-Q200 Grade 0, 0402", Manufacturer=Vishay-Dale, Power_W=63mW, Supplier Part Number 1=541-2.49KLCT-ND, TempCo="100 ppm/C", Tolerance_%=1%, Value2=0.063W, Value_Code=2k49, ValueDisplayed=2.49k
R262 R266: library part Resistor, "RES,470, 5%, 0.1 W, AEC-Q200 Grade 0, 0402", Manufacturer=Panasonic, Power_W=100mW, Supplier Part Number 1=P510JCT-ND, TempCo="200 ppm/C", Tolerance_%=5%, Value2=0.1W, Value_Code=510R, ValueDisplayed=470
R263: library part Resistor, "RES, 510, 5%, 0.1 W, AEC-Q200 Grade 0, 0402", Manufacturer=Panasonic, Power_W=100mW, Supplier Part Number 1=P510JCT-ND, TempCo="200 ppm/C", Tolerance_%=5%, Value2=0.1W, Value_Code=510R, ValueDisplayed=470
R275 R281: library part Resistor, "RES, 1.00 k, 1%, 0.25 W, 0805", Manufacturer=Panasonic, Power_W=250mW, Supplier Part Number 1=P16058CT-ND, TempCo="100 ppm/C", Tolerance_%=1%, Value2=0.25W, Value_Code=1k00, ValueDisplayed=1.00k
R276: library part Resistor, "RES, 4.7k, 1%, 0.063 W, AEC-Q200 Grade 0, 0402", Manufacturer=Vishay-Dale, Power_W=63mW, Supplier Part Number 1=541-2.94KLCT-ND, TempCo="100 ppm/C", Tolerance_%=1%, Value2=0.063W, Value_Code=2k94, ValueDisplayed=4.7k
R277: library part Resistor, "RES, 4.7 k, 1%, 0.063 W, AEC-Q200 Grade 0, 0402", Manufacturer=Vishay-Dale, Power_W=63mW, Supplier Part Number 1=541-2.94KLCT-ND, TempCo="100 ppm/C", Tolerance_%=1%, Value2=0.063W, Value_Code=2k94, ValueDisplayed=4.7k
R278 R279: library part Resistor, "RES, 100 k, 1%, 0.063 W, AEC-Q200 Grade 0, 0402", Manufacturer=Vishay-Dale, Power_W=63mW, Supplier Part Number 1=541-100KLCT-ND, TempCo="100 ppm/C", Tolerance_%=1%, Value2=0.063W, Value_Code=100k
R280: library part Resistor, "RES, 4.7 k, 5%, 0.063 W, AEC-Q200 Grade 0, 0402", Manufacturer=Vishay-Dale, Power_W=63mW, Supplier Part Number 1=541-2.2KJCT-ND, TempCo="200 ppm/C", Tolerance_%=5%, Value2=0.063W, Value_Code=2k20, ValueDisplayed=4.7k
R282: library part Resistor, "RES, 100 k, 5%, 0.125 W, AEC-Q200 Grade 0, 0805", Manufacturer=Vishay-Dale, Power_W=125mW, Supplier Part Number 1=541-100KACT-ND, TempCo="200 ppm/C", Tolerance_%=5%, Value2=0.125W, Value_Code=100k
R347: library part Resistor, "RES, 470, 5%, 0.1 W, AEC-Q200 Grade 0, 0402", Manufacturer=Panasonic, Power_W=100mW, Supplier Part Number 1=P510JCT-ND, TempCo="200 ppm/C", Tolerance_%=5%, Value2=0.1W, Value_Code=510R, ValueDisplayed=470
R350: library part CMP-0025958-3, "RES, 10.0 k, 1%, 0.063 W, AEC-Q200 Grade 0, 0402", Manufacturer=Vishay-Dale, PartNumber=CRCW040210K0FKED, Power_W=63mW, Supplier Part Number 1=541-10.0KLCT-ND, TempCo="100 ppm/C", Tolerance_%=1%, Value2=0.063W, Value_Code=10k0, ValueDisplayed=NC.10.0k
R386: library part Resistor, "RES, 33.2, 1%, 0.063 W, AEC-Q200 Grade 0, 0402", Manufacturer=Vishay-Dale, Power_W=63mW, Supplier Part Number 1=541-33.2LCT-ND, TempCo="100 ppm/C", Tolerance_%=1%, Value2=0.063W, Value_Code=33R2, ValueDisplayed=33.2
Rs301 Rs303: library part CMP-0025958-3, "NC RES, 10.0 k, 1%", Manufacturer=Vishay-Dale, Power_W=63mW, Supplier Part Number 1=541-10.0KLCT-ND, TempCo="100 ppm/C", Tolerance_%=1%, Value2=0.063W, Value_Code=10k0, ValueDisplayed="NC 10.0k"
TP8: library part CMP-0078143-3, "TEST POINT.  No entry in BOM.", Manufacturer=N/A
TRS1: library part INDUCTORCAN
U5: library part CMP-0089855-1, "Low-Power Fault Protected CAN FD Transceiver with INH and WAKE", Manufacturer="Texas Instruments", Max Supply Voltage=28V, Min Supply Voltage=1.7V, Operating Temperature Range="-40°C to +125°C"
U6: library part SCT2632Q, JLCPCB Part Class="Extended Part", LCSC Part Name=SCT2632STER, Manufacturer=SCT(芯洲科技)
U8: library part SYM-LP8774RXVRQ1, "Three Buck Converters and 5-V Boost for AWR and IWR Radar Sensors", Manufacturer="Texas Instruments", Max Supply Voltage=4V, Min Supply Voltage=3V, Nominal Supply Current=3uA, Operating Temperature Range="-40°C to +150°C", Output Voltage=0.9-1.9V, Switching Frequency=4.4-8.8-17.6MHz
U9: library part SYM-GD25B64CWAG, "3.3V Uniform Sector Dual and Quad Serial Flash SPI 64Mbit 2.7-3.6V WSON8", Frequency_Fixed=120MHz, Manufacturer=GigaDevice, Max Supply Voltage=3.6V, Min Supply Voltage=2.7V, Nominal Supply Current=13-15mA, Operating Temperature Range="-40°C to +125°C"
U15: library part CMP-0089064-1, "TC-10 Compliant 100Base-T1 Automotive Ethernet PHY", Manufacturer="Texas Instruments", Operating Temperature Range="-40°C to +125°C"
U27: library part CMP-0092338-1, "Linear Voltage Regulator IC Positive Fixed Output 300mA SOT-23-5", Digikey Part Number=296-TPS78417QDBVRQ1CT-ND, Dropout Voltage=900mV, Manufacturer="Texas Instruments", Max Supply Voltage=6V, Min Supply Voltage=1.65V, Mouser Part Number=595-TPS78417QDBVRQ1, Nominal Supply Current=0.033mA, Operating Temperature Range="-40°C to +150°C", Output Voltage=1.7V
U29: library part CMP-0091573-4, Manufacturer="Texas Instruments", Operating Temperature Range=to
UCAN1: library part 82C250, "82C250"
Y3: library part CMP-0090505-1, "40MHz ±10ppm Crystal 8pF 50 Ohms 4-SMD, No Lead", Digikey Part Number=FW4000044QDICT-ND, Frequency Stability=50ppm, Frequency Tolerance=10ppm, Frequency_Fixed=40MHz, Load Capacitance=8pF, Manufacturer=Diodes, Mouser Part Number=729-FW4000044Q, Operating Temperature Range="-40°C to +125°C"
YE7: library part CRYSTAL

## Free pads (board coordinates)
  round 30 smd mask+4: 2(1734.91,656.78) 27(1098.23,1389.9) 27(1138.23,1429.02) 27(1213.58,1301.68) 28(1261.42,1300.51) 29(1250.37,1354.81) 30(1345.16,1336.79) 39(120.67,1071.72) 39(133.3,327.02) 39(836.84,1195.02) 39(1021.65,614.87)
  oval 25x30 smd mask+4: 3(1744.56,489.86) 4(1771.34,426.3) 15(1681.51,432.75) 16(1594.14,465.85) 16(1625.09,387.22) 19(1563.91,415.04) 20(1533.63,342.26) 21(1393.26,331.76) 21(1497.54,379.3) 25(997.69,747.06) 26(1031.19,726.29) 31(1250.13,666.76) 32(1426.64,390.46) 33(1459.88,322.16) 34(1654.08,331.76)
  round 25 smd far side mask+4: 5(1487.63,525.26) 6(1521.54,493.3) 8(1377.67,615.52) 8(1427.21,606.44) 9(1340.25,660.47)
  oval 30x25 smd far side mask+4: 35(2096.22,707.13) 37(1961.09,789.27)
  oval 25x30 smd far side mask+4: 36(2035.53,666.78)
  round 50 smd mask+4: 38(377.56,2419.35) 38(1960.71,128.74) 38(3059.98,108.87)
  oval 35x30 smd mask+4: 40(1916.23,775.93)
  oval 30x35 smd far side mask+4: 41(517.41,2081.02)
  oval 25x30 smd far side rot 135 mask+4: 42(915.03,2038.81)
  round 196.85 hole 125.98: ""(145.67,145.67) ""(145.67,2401.57) ""(3405.51,145.67) ""(3405.51,2401.57)
  round 78.74 hole 78.74: ""(251.97,2283.46) ""(3478.35,291.34)

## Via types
v1: diameter 13.77, hole 5.9, Top Layer to GND1, tented both sides, 427 vias
v2: diameter 18, hole 8, Top Layer to Bottom Layer, tented both sides, 341 vias
v3: diameter 13.77/13.77 (per signal layer), hole 5.9, Top Layer to GND1, tented both sides, 229 vias
v4: diameter 20, hole 12, Top Layer to Bottom Layer, tented both sides, 165 vias
v5: diameter 13.77, hole 5.9, Top Layer to GND1, tented top, 140 vias
v6: diameter 20, hole 10, Top Layer to Bottom Layer, tented both sides, 19 vias
v7: diameter 32, hole 20, Top Layer to Bottom Layer, tented both sides, 9 vias
v8: diameter 28, hole 16, Top Layer to Bottom Layer, tented both sides, 9 vias
v9: diameter 19.68, hole 7.87, Top Layer to Bottom Layer, tented both sides, 1 vias

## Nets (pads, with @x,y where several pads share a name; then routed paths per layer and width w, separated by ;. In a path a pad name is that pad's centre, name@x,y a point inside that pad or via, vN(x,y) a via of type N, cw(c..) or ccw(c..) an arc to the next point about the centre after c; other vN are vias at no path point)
1V0: C114.1 C115.2 C116.1 C117.2 C179.1 C179.3 C181.1 C181.3 pad.39@120.67,1071.72 R73.2 R111.2 R133.2 U29.D6 U29.D7 U29.M4 | length 421.7
  Top Layer w13: v2(1446.97,1132.05) 1454.74,1125.58 U29.M4@1459.76,1121.4 1464.78,1125.58 v2(1472.56,1132.05) ; v2(1675.14,1031.83) 1668.67,1039.61 U29.D7@1664.49,1044.63 U29.D6@1664.49,1070.22 ; U29.D6@1664.49,1070.22 1668.67,1075.24 v2(1675.14,1083.01) U29.D6@1664.49,1070.22
  Top Layer w15: v6(1031.19,1274.49) 1031.19,1279.3 1031.52,1279.64 C179.3@1031.52,1305.06 ; C179.1@1094.52,1305.06 1094.52,1299.25 1094.99,1298.78 1094.99,1275.08 1097.2,1272.87 v6(1097.2,1271.52)
  PWR1 w10: v2(1675.14,1031.83) 1781.3,1031.83
  Bottom Layer w10: R133.2@1244.24,1583.69 R133.2@1245.07,1582.86 ; R133.2@1245.07,1583.27 v2(1245.07,1619.98) ; C181.3@1638.93,1025.69 C181.3@1643.93,1025.69 1669,1025.69 v2(1675.14,1031.83) ; C181.1@1638.93,1088.69 C181.1@1643.93,1088.69 1669.47,1088.69 v2(1675.14,1083.01) 1676,1083.88 C117.2@1700.89,1083.88
  other v6: 47.24,1026.15 78.49,1026.07 47.51,1062.1 77.84,1062.72 47.3,1100.66 78.16,1100.34 78.84,1139.08
1V0_ETH2: pad.41 pad.42 U15.9 U15.21 | length 729.4
  PWR1 w10.6: v4(594.35,2044.92) 819.31,2044.92 881.43,1982.79 v4(881.43,1941.88)
  Bottom Layer w10.6: pad.41@517.41,2081.02 517.41,2050.66 551.26,2016.82 ; U15.9@587.86,1971.25 562.75,1971.25 551.26,1982.74 551.26,2016.82 ; v4(594.35,2044.92) 592.55,2043.12 572.62,2043.12 551.26,2021.75 551.26,2016.82 ; U15.21@832.05,1931.88 871.43,1931.88 v4(881.43,1941.88) 899.97,1960.42 899.97,2023.75 pad.42@915.03,2038.81
1V2: C92.2 C96.2 C137.2 C138.2 C139.2 C140.2 C141.2 C142.2 C146.2 pad.39@133.3,327.02 R30.2 R315.2 U29.E12 U29.E13 U29.E14 U29.F14 U29.H14 U29.J14 U29.K14 U29.L14 U29.N6 U29.N14 U29.P6 U29.P7 U29.P9 U29.P10 U29.P11 U29.P13 U29.P14 U29.V7 U29.V13 | length 2211.9
  Top Layer w10: C92.2@1167.79,1034.18 1172.63,1029.34 1181.63,1029.34 1184.51,1026.46 1204.21,1026.46 1208.21,1022.46 1261.77,1022.46 1283.45,1044.14 1305.73,1044.14 U29.V7@1306.22,1044.63 ; v2(1285.36,894.09) 1288.36,891.09 U29.V13@1306.22,891.09
  Top Layer w13: U29.P13@1408.58,891.09 1412.76,886.07 v2(1419.23,878.29) ; U29.P11@1408.58,942.27 1403.56,946.45 v2(1395.79,952.92) 1404.32,962.89 U29.P10@1408.58,967.86 1404.4,972.88 v2(1397.93,980.65) 1404.4,988.43 U29.P9@1408.58,993.45 ; v2@1421.95,853.71 1419.23,856.43 v2@1419.23,856.62 ; v2@1424.65,1060.69 v2@1422.72,1060.69 ; U29.N14@1433.81,865.5 U29.N14@1433.85,865.46 ; U29.N6@1434.17,1070.22 1429.15,1066.04 v2@1422.72,1060.69 ; U29.L14@1485.35,865.5 v2@1498.16,854.67 ; v2(1498.27,854.79) U29.K14@1510.94,865.5 U29.J14@1536.53,865.5 1541.53,861.27 v2@1549.33,854.68 ; U29.H14@1562.12,865.5 v2@1549.46,854.78 ; U29.F14@1613.31,865.5 1618.27,869.75 1628.24,878.29 ; U29.E14@1638.9,865.5 1634.72,870.52 1628.24,878.29 ; U29.E12@1638.9,916.68 1634.72,911.66 v2(1628.24,903.88) 1634.72,896.11 U29.E13@1638.9,891.09 1634.72,886.07 1628.24,878.29 ; v2(1397.93,1057.42) 1401.19,1060.69 v2@1420.03,1060.69 ; v2(1397.93,1057.42) 1404.4,1065.2 U29.P6@1408.58,1070.22 1413.6,1066.04 v2@1420.03,1060.69 ; v2(1397.93,1057.42) 1404.4,1049.65 U29.P7@1408.58,1044.63 1412.84,1049.6 v2(1421.38,1059.57) ; v2@1419.23,856.62 v2(1419.23,878.29) ; v2@1419.23,856.62 v2(1421.38,854.84) 1429.15,861.32 U29.N14@1434.17,865.5 1429.2,869.75 v2(1419.23,878.29) ; v2@1419.23,856.62 1413.6,861.32 U29.P14@1408.58,865.5 1412.76,870.52 v2(1419.23,878.29) ; v2@1420.03,1060.69 v2@1422.72,1060.69 ; v2@1420.03,1060.69 v2(1421.38,1059.57) ; v2(1421.38,1059.57) v2@1422.72,1060.69 ; v2@1549.33,854.68 v2@1549.46,854.78 ; v2@1549.33,854.68 v2@1549.46,854.78
  PWR2 w20: v2(1093.94,1580.34) 996.65,1483.05 996.65,1404.03 916.52,1323.9 824.95,1323.9 788.27,1287.22 788.27,1088.68 853.29,1023.66 1199.19,1023.66 v2(1199.56,1023.29)
  Bottom Layer w10: v2(1093.94,1580.34) 1125.23,1580.34 R315.2@1128.42,1583.52
  Bottom Layer w15: C146.2@1188.42,883.25 1273.71,883.25 1284.55,894.09 v2(1285.36,894.09) ; C138.2@1382.37,929.47 1395.79,942.89 v2(1395.79,952.92) 1397.93,955.06 v2(1397.93,980.65) ; v2(1397.93,1057.42) 1400.07,1059.57 v2(1421.38,1059.57) 1423.3,1057.64 C139.2@1423.3,1033 ; v2(1421.38,854.84) 1419.23,856.98 v2(1419.23,878.29) 1419.44,878.09 C142.2@1447.64,878.09 ; v2@1498.15,854.68 1516.06,854.68 C141.2@1524.6,863.21 ; v2@1549.33,854.68 1563.06,854.68 C140.2@1573.44,865.06 ; C140.2@1572.83,865.68 C140.2@1573.44,865.06 ; v2(1628.24,903.88) 1628.24,878.29 1605.79,855.83 1582.67,855.83 C140.2@1573.44,865.06
  other v2: 75.18,346.35 109.15,346.35 42.22,380.32 74.77,380.12 108.52,380.26 42.02,414.29 73.96,414.09 106.78,414.34 64.71,535.76 103.72,535.76 1549.45,854.79 1199.56,1046
1V4_APLL: C103.1 U29.H4 | length 45.1
  Top Layer w10.6: v2(1549.33,1110.75) 1557.1,1117.22 U29.H4@1562.12,1121.4
  Bottom Layer w15: v2(1549.33,1110.75) 1560.84,1110.75 C103.1@1572.83,1098.76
